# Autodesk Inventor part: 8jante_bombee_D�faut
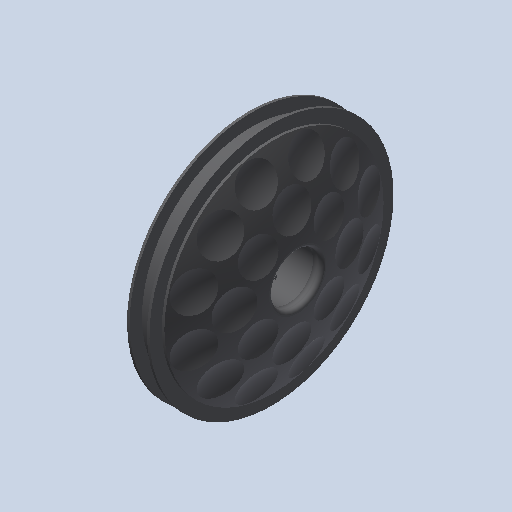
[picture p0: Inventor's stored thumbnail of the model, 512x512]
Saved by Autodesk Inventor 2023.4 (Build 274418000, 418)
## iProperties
Created: 2011-01
Part Number: 8jante_bombee_D�faut
Document SubType Name: Modeling
Designer: eric
Density: 1 g/cm^3
Mass: 137.725 g
Surface Area: 1288.94 cm^2
Volume: 137.725 cm^3
Material: Générique
Appearance: Yellow
Author: eric
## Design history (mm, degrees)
feature "Base1"
node "Corps solides"
node "Corps surfaciques"
node "Solide1"
